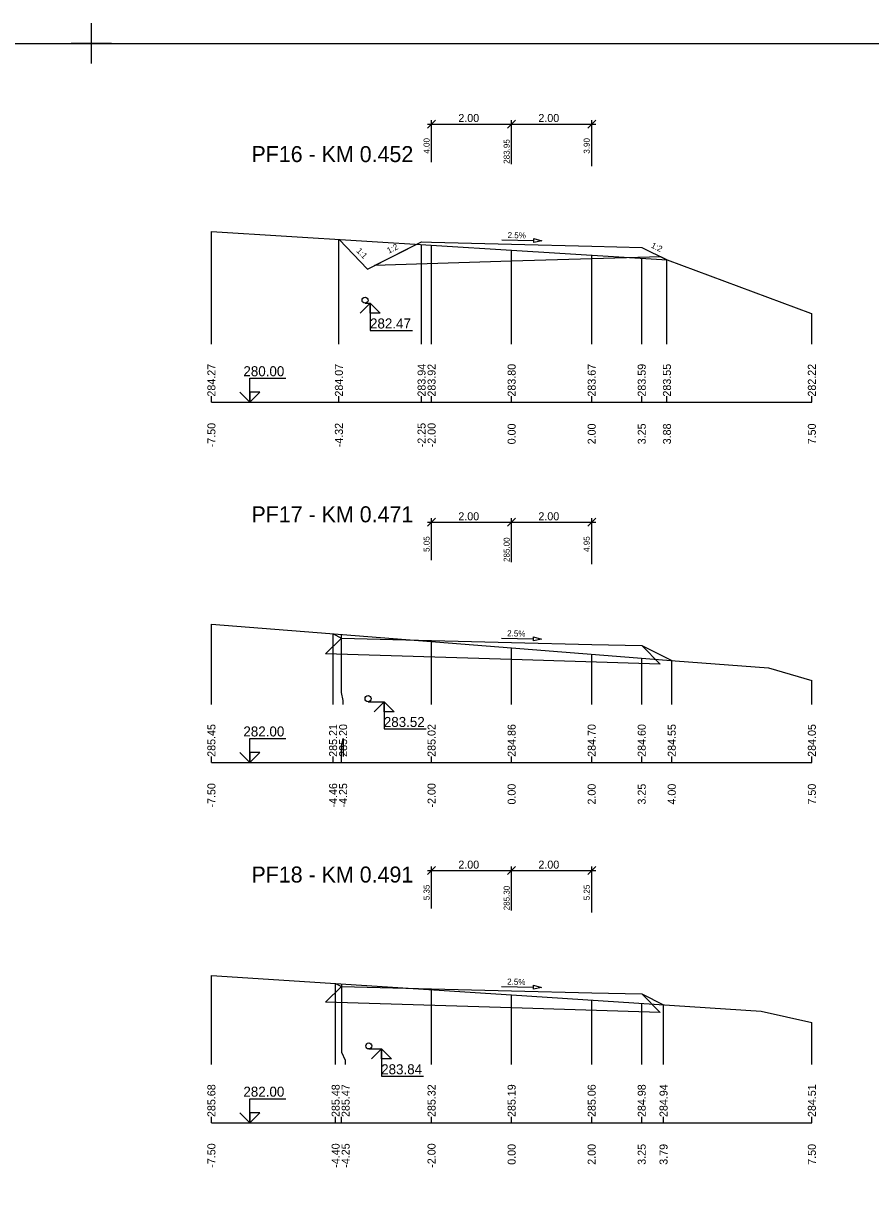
# Model space of a CAD drawing. Extents: x -5 to 1895, y -2 to 602.
# Drawn here: x 1033 to 1244.7, y 310.3 to 601.7 of the extents above; entities that cross this region are included whole.
import ezdxf

# ---------------------------------------------------------------- set-up
doc = ezdxf.new("R2010")
doc.units = 0
for name, color, linetype in [('KOTA', 7, 'Continuous'), ('KOTA_DELKY', 7, 'Continuous'), ('KOTA_DELKY_CONT', 7, 'Continuous'), ('KRIZENI', 7, 'Continuous'), ('NS_TELESO_VOZOVKY', 7, 'Continuous'), ('NS_V_PF', 7, 'Continuous'), ('REZY_PF_PUVODNI', 7, 'Continuous'), ('SESTAVY_REZU_PF', 7, 'Continuous'), ('SKLON', 7, 'Continuous'), ('SVK', 7, 'Continuous')]:
    doc.layers.add(name, color=color, linetype=linetype)

msp = doc.modelspace()

# ---------------------------------------------------------------- linework, layer by layer
for p, q in [((1050, 601.67), (1050, 591.67)), ((1050, 601.67), (1050, 591.67)), ((1050, 601.67), (1050, 591.67)), ((1050, 601.67), (1050, 591.67)), ((1050, 601.67), (1050, 591.67)), ((1050, 601.67), (1050, 591.67)), ((1050, 601.67), (1050, 591.67)), ((1050, 601.67), (1050, 591.67)), ((1050, 601.67), (1050, 591.67)), ((1050, 601.67), (1050, 591.67)), ((1050, 601.67), (1050, 591.67)), ((1050, 601.67), (1050, 591.67)), ((1050, 601.67), (1050, 591.67)), ((1050, 601.67), (1050, 591.67)), ((1050, 601.67), (1050, 591.67)), ((1050, 601.67), (1050, 591.67)), ((1050, 601.67), (1050, 591.67)), ((1050, 601.67), (1050, 591.67)), ((1050, 601.67), (1050, 591.67)), ((1050, 601.67), (1050, 591.67)), ((1050, 601.67), (1050, 591.67)), ((1050, 601.67), (1050, 591.67)), ((1050, 601.67), (1050, 591.67)), ((1050, 601.67), (1050, 591.67)), ((1050, 601.67), (1050, 591.67)), ((1050, 601.67), (1050, 591.67)), ((1050, 601.67), (1050, 591.67)), ((1050, 601.67), (1050, 591.67)), ((1050, 601.67), (1050, 591.67)), ((1050, 601.67), (1050, 591.67)), ((1050, 601.67), (1050, 591.67)), ((1050, 601.67), (1050, 591.67)), ((1050, 601.67), (1050, 591.67)), ((1050, 601.67), (1050, 591.67)), ((1050, 601.67), (1050, 591.67)), ((1050, 601.67), (1050, 591.67)), ((1050, 601.67), (1050, 591.67)), ((1050, 601.67), (1050, 591.67)), ((1050, 601.67), (1050, 591.67)), ((1050, 601.67), (1050, 591.67)), ((1050, 601.67), (1050, 591.67)), ((1050, 601.67), (1050, 591.67)), ((1050, 601.67), (1050, 591.67)), ((1050, 601.67), (1050, 591.67)), ((1050, 601.67), (1050, 591.67)), ((1050, 601.67), (1050, 591.67)), ((1050, 601.67), (1050, 591.67)), ((1050, 601.67), (1050, 591.67)), ((1050, 601.67), (1050, 591.67)), ((1050, 601.67), (1050, 591.67)), ((1050, 601.67), (1050, 591.67)), ((1050, 601.67), (1050, 591.67)), ((1050, 601.67), (1050, 591.67)), ((1050, 601.67), (1050, 591.67)), ((1055, 596.67), (1045, 596.67)), ((1055, 596.67), (1045, 596.67)), ((1055, 596.67), (1045, 596.67)), ((1055, 596.67), (1045, 596.67)), ((1055, 596.67), (1045, 596.67)), ((1055, 596.67), (1045, 596.67)), ((1055, 596.67), (1045, 596.67)), ((1055, 596.67), (1045, 596.67)), ((1055, 596.67), (1045, 596.67)), ((1055, 596.67), (1045, 596.67)), ((1055, 596.67), (1045, 596.67)), ((1055, 596.67), (1045, 596.67)), ((1055, 596.67), (1045, 596.67)), ((1055, 596.67), (1045, 596.67)), ((1055, 596.67), (1045, 596.67)), ((1055, 596.67), (1045, 596.67)), ((1055, 596.67), (1045, 596.67)), ((1055, 596.67), (1045, 596.67)), ((1055, 596.67), (1045, 596.67)), ((1055, 596.67), (1045, 596.67)), ((1055, 596.67), (1045, 596.67)), ((1055, 596.67), (1045, 596.67)), ((1055, 596.67), (1045, 596.67)), ((1055, 596.67), (1045, 596.67)), ((1055, 596.67), (1045, 596.67)), ((1055, 596.67), (1045, 596.67)), ((1055, 596.67), (1045, 596.67)), ((1055, 596.67), (1045, 596.67)), ((1055, 596.67), (1045, 596.67)), ((1055, 596.67), (1045, 596.67)), ((1055, 596.67), (1045, 596.67)), ((1055, 596.67), (1045, 596.67)), ((1055, 596.67), (1045, 596.67)), ((1055, 596.67), (1045, 596.67)), ((1055, 596.67), (1045, 596.67)), ((1055, 596.67), (1045, 596.67)), ((1055, 596.67), (1045, 596.67)), ((1055, 596.67), (1045, 596.67)), ((1055, 596.67), (1045, 596.67)), ((1055, 596.67), (1045, 596.67)), ((1055, 596.67), (1045, 596.67)), ((1055, 596.67), (1045, 596.67)), ((1055, 596.67), (1045, 596.67)), ((1055, 596.67), (1045, 596.67)), ((1055, 596.67), (1045, 596.67)), ((1055, 596.67), (1045, 596.67)), ((1055, 596.67), (1045, 596.67)), ((1055, 596.67), (1045, 596.67)), ((1055, 596.67), (1045, 596.67)), ((1055, 596.67), (1045, 596.67)), ((1055, 596.67), (1045, 596.67)), ((1055, 596.67), (1045, 596.67)), ((1055, 596.67), (1045, 596.67)), ((1055, 596.67), (1045, 596.67))]:
    msp.add_line(p, q)
msp.add_lwpolyline([(0, 596.67), (1890, 596.67), (1890, 2.67), (0, 2.67)], close=True)
at = {"layer": 'KOTA'}
for points in [[(1119.66, 531.75), (1117.16, 529.25), (1119.66, 531.75), (1119.66, 524.93), (1130.2, 524.93)], [(1118.38, 531.75), (1119.74, 531.75)], [(1119.66, 531.75), (1122.16, 529.25), (1119.66, 529.25), (1119.66, 531.75)], [(1119.66, 531.75), (1122.16, 529.25), (1119.66, 529.25)], [(1089.57, 507), (1087.07, 509.5), (1089.57, 507), (1089.57, 513), (1098.57, 513)], [(1089.57, 507), (1092.07, 509.5), (1089.57, 509.5), (1089.57, 507)], [(1089.57, 507), (1092.07, 509.5), (1089.57, 509.5)], [(1119.13, 432.19), (1123.12, 432.19)], [(1123.12, 432.19), (1120.62, 429.69), (1123.12, 432.19), (1123.12, 425.37), (1133.66, 425.37)], [(1123.12, 432.19), (1125.62, 429.69), (1123.12, 429.69), (1123.12, 432.19)], [(1123.12, 432.19), (1125.62, 429.69), (1123.12, 429.69)], [(1089.57, 417), (1087.07, 419.5), (1089.57, 417), (1089.57, 423), (1098.57, 423)], [(1089.57, 417), (1092.07, 419.5), (1089.57, 419.5), (1089.57, 417)], [(1089.57, 417), (1092.07, 419.5), (1089.57, 419.5)], [(1119.32, 345.43), (1122.46, 345.43)], [(1122.46, 345.43), (1119.96, 342.93), (1122.46, 345.43), (1122.46, 338.6), (1133, 338.6)], [(1122.46, 345.43), (1124.96, 342.93), (1122.46, 342.93), (1122.46, 345.43)], [(1122.46, 345.43), (1124.96, 342.93), (1122.46, 342.93)], [(1089.57, 327), (1087.07, 329.5), (1089.57, 327), (1089.57, 333), (1098.57, 333)], [(1089.57, 327), (1092.07, 329.5), (1089.57, 329.5), (1089.57, 327)], [(1089.57, 327), (1092.07, 329.5), (1089.57, 329.5)]]:
    msp.add_lwpolyline(points, dxfattribs=at)
at = {"layer": 'KOTA_DELKY'}
for points in [[(1134, 575.51), (1136, 577.51)], [(1135, 567.01), (1135, 577.51)], [(1154, 575.51), (1156, 577.51)], [(1154, 575.51), (1156, 577.51)], [(1155, 566.51), (1155, 577.51)], [(1155, 566.51), (1155, 577.51)], [(1174, 575.51), (1176, 577.51)], [(1175, 566.01), (1175, 577.51)], [(1134, 576.51), (1156, 576.51)], [(1154, 576.51), (1176, 576.51)], [(1134, 476.01), (1136, 478.01)], [(1135, 467.51), (1135, 478.01)], [(1154, 476.01), (1156, 478.01)], [(1154, 476.01), (1156, 478.01)], [(1155, 467.01), (1155, 478.01)], [(1155, 467.01), (1155, 478.01)], [(1174, 476.01), (1176, 478.01)], [(1175, 466.51), (1175, 478.01)], [(1134, 477.01), (1156, 477.01)], [(1154, 477.01), (1176, 477.01)], [(1134, 388.98), (1136, 390.98)], [(1135, 380.48), (1135, 390.98)], [(1154, 388.98), (1156, 390.98)], [(1154, 388.98), (1156, 390.98)], [(1155, 379.98), (1155, 390.98)], [(1155, 379.98), (1155, 390.98)], [(1174, 388.98), (1176, 390.98)], [(1175, 379.48), (1175, 390.98)], [(1134, 389.98), (1156, 389.98)], [(1154, 389.98), (1176, 389.98)]]:
    msp.add_lwpolyline(points, dxfattribs=at)
at = {"layer": 'KRIZENI'}
for centre in [(1118.38, 532.5), (1119.13, 432.94), (1119.32, 346.18)]:
    msp.add_circle(centre, 0.75, dxfattribs=at)
at = {"layer": 'NS_TELESO_VOZOVKY'}
for points in [[(1155, 546.51), (1175, 546.01), (1187.5, 545.69), (1193.8, 542.54), (1192.24, 543.32), (1155, 542.21), (1120.78, 541.18), (1132.5, 547.07), (1135, 547.01), (1155, 546.51)], [(1155, 447.01), (1175, 446.51), (1187.5, 446.2), (1192.1, 441.6), (1155, 442.71), (1108.53, 444.11), (1112.5, 448.08), (1135, 447.51), (1155, 447.01)], [(1155, 359.98), (1175, 359.48), (1187.5, 359.17), (1192.1, 354.57), (1155, 355.68), (1108.53, 357.08), (1112.5, 361.04), (1135, 360.48), (1155, 359.98)]]:
    msp.add_lwpolyline(points, dxfattribs=at)
at = {"layer": 'NS_V_PF'}
for points in [[(1111.88, 547.68), (1118.97, 540.27), (1132.5, 547.07), (1135, 547.01), (1155, 546.51), (1175, 546.01), (1187.5, 545.69), (1193.8, 542.54)], [(1110.4, 449.13), (1112.5, 448.08), (1135, 447.51), (1155, 447.01), (1175, 446.51), (1187.5, 446.2), (1195, 442.45)], [(1111.03, 361.78), (1112.5, 361.04), (1135, 360.48), (1155, 359.98), (1175, 359.48), (1187.5, 359.17), (1192.95, 356.45)]]:
    msp.add_lwpolyline(points, dxfattribs=at)
at = {"layer": 'REZY_PF_PUVODNI'}
for points in [[(1080, 549.68), (1155, 544.98), (1193.87, 542.54), (1197.41, 541.25), (1229.63, 529.25), (1230, 529.19)], [(1080, 451.53), (1155, 445.61), (1195.84, 442.39), (1219.19, 440.63), (1230, 437.52)], [(1080, 363.8), (1155, 358.92), (1217.3, 354.86), (1230, 352.06)]]:
    msp.add_lwpolyline(points, dxfattribs=at)
at = {"layer": 'SESTAVY_REZU_PF'}
for points in [[(1080, 507), (1230, 507)], [(1080, 417), (1230, 417)], [(1080, 327), (1230, 327)]]:
    msp.add_lwpolyline(points, dxfattribs=at)
at = {"layer": 'SKLON'}
for points in [[(1160.56, 547.87), (1162.54, 547.32), (1160.53, 546.87)], [(1160.46, 448.38), (1162.45, 447.83), (1160.43, 447.38)], [(1160.46, 361.35), (1162.45, 360.8), (1160.43, 360.35)]]:
    msp.add_lwpolyline(points, close=True, dxfattribs=at)
for points in [[(1160.56, 547.87), (1162.54, 547.32), (1160.53, 546.87), (1160.56, 547.87)], [(1152.55, 547.57), (1160.54, 547.37)], [(1152.45, 448.08), (1160.45, 447.88)], [(1160.46, 448.38), (1162.45, 447.83), (1160.43, 447.38), (1160.46, 448.38)], [(1160.46, 361.35), (1162.45, 360.8), (1160.43, 360.35), (1160.46, 361.35)], [(1152.45, 361.05), (1160.45, 360.85)]]:
    msp.add_lwpolyline(points, dxfattribs=at)
at = {"layer": 'SVK'}
for points in [[(1080, 521.5), (1080, 549.68)], [(1111.85, 521.5), (1111.85, 547.69)], [(1132.5, 521.5), (1132.5, 546.39)], [(1135, 521.5), (1135, 546.23)], [(1155, 521.5), (1155, 544.98)], [(1175, 521.5), (1175, 543.72)], [(1187.5, 521.5), (1187.5, 542.94)], [(1193.8, 521.5), (1193.8, 542.54)], [(1230, 521.5), (1230, 529.19)], [(1080, 507), (1080, 508.5)], [(1111.85, 507), (1111.85, 508.5)], [(1132.5, 507), (1132.5, 508.5)], [(1135, 507), (1135, 508.5)], [(1155, 507), (1155, 508.5)], [(1175, 507), (1175, 508.5)], [(1187.5, 507), (1187.5, 508.5)], [(1193.8, 507), (1193.8, 508.5)], [(1230, 507), (1230, 508.5)], [(1080, 431.5), (1080, 451.53)], [(1110.4, 431.5), (1110.4, 449.13)], [(1112.9, 431.5), (1112.9, 432.5), (1112.5, 434.5), (1112.5, 448.96)], [(1135, 431.5), (1135, 447.19)], [(1155, 431.5), (1155, 445.61)], [(1175, 431.5), (1175, 444.03)], [(1187.5, 431.5), (1187.5, 443.04)], [(1195, 431.5), (1195, 442.45)], [(1230, 431.5), (1230, 437.52)], [(1112.5, 417), (1112.5, 421), (1112.9, 423), (1112.9, 418.5)], [(1080, 417), (1080, 418.5)], [(1110.4, 417), (1110.4, 418.5)], [(1135, 417), (1135, 418.5)], [(1155, 417), (1155, 418.5)], [(1175, 417), (1175, 418.5)], [(1187.5, 417), (1187.5, 418.5)], [(1195, 417), (1195, 418.5)], [(1230, 417), (1230, 418.5)], [(1080, 341.5), (1080, 363.8)], [(1111.03, 341.5), (1111.03, 361.78)], [(1113.53, 341.5), (1113.53, 342.5), (1112.55, 344.5), (1112.55, 361.68)], [(1135, 341.5), (1135, 360.22)], [(1155, 341.5), (1155, 358.92)], [(1175, 341.5), (1175, 357.61)], [(1187.5, 341.5), (1187.5, 356.8)], [(1192.95, 341.5), (1192.95, 356.45)], [(1230, 341.5), (1230, 352.06)], [(1080, 327), (1080, 328.5)], [(1111.03, 327), (1111.03, 328.5)], [(1112.53, 326.99), (1112.53, 328.35), (1112.53, 328.47), (1112.53, 328.47)], [(1135, 327), (1135, 328.5)], [(1155, 327), (1155, 328.5)], [(1175, 327), (1175, 328.5)], [(1187.5, 327), (1187.5, 328.5)], [(1192.95, 327), (1192.95, 328.5)], [(1230, 327), (1230, 328.5)]]:
    msp.add_lwpolyline(points, dxfattribs=at)

# ---------------------------------------------------------------- texts
at = {"layer": 'KOTA'}
for s, p in [('282.47', (1119.62, 525.43)), ('280.00', (1087.99, 513.5)), ('283.52', (1123.07, 425.87)), ('282.00', (1087.99, 423.5)), ('283.84', (1122.41, 339.1)), ('282.00', (1087.99, 333.5))]:
    msp.add_text(s, height=2.5, dxfattribs=at).set_placement(p)
at = {"layer": 'KOTA_DELKY'}
for p in [(1141.69, 577.01), (1161.69, 577.01), (1141.69, 477.51), (1161.69, 477.51), (1141.69, 390.48), (1161.69, 390.48)]:
    msp.add_text('2.00', height=2, dxfattribs=at).set_placement(p)
at = {"layer": 'KOTA_DELKY_CONT'}
for s, p in [('4.00', (1134.5, 569.1)), ('283.95', (1154.5, 566.58)), ('3.90', (1174.5, 569.1)), ('5.05', (1134.5, 469.6)), ('285.00', (1154.5, 467.09)), ('4.95', (1174.5, 469.6)), ('5.35', (1134.5, 382.57)), ('285.30', (1154.5, 380.06)), ('5.25', (1174.5, 382.57))]:
    msp.add_text(s, height=1.5, rotation=90, dxfattribs=at).set_placement(p)
at = {"layer": 'SESTAVY_REZU_PF'}
for s, p in [('PF16 - KM 0.452', (1090, 567)), ('PF17 - KM 0.471', (1090, 477)), ('PF18 - KM 0.491', (1090, 387))]:
    msp.add_text(s, height=4, dxfattribs=at).set_placement(p)
at = {"layer": 'SKLON'}
for s, rotation, p in [('2.5%', 358.5679, (1153.97, 548.03)), ('1:1', 313.6939, (1116.11, 544.71)), ('1:2', 26.6859, (1124.32, 544.08)), ('1:2', 333.4349, (1189.69, 545.72)), ('2.5%', 358.5679, (1153.87, 448.54)), ('2.5%', 358.5679, (1153.87, 361.51))]:
    msp.add_text(s, height=1.5, rotation=rotation, dxfattribs=at).set_placement(p)
at = {"layer": 'SVK'}
for s, p in [(' 284.27', (1081, 507.67)), (' 284.07', (1112.85, 507.67)), (' 283.94', (1133.5, 507.67)), (' 283.92', (1136, 507.67)), (' 283.80', (1156, 507.67)), (' 283.67', (1176, 507.67)), (' 283.59', (1188.5, 507.67)), (' 283.55', (1194.8, 507.67)), (' 282.22', (1231, 507.67)), (' -7.50', (1081, 495)), (' -4.32', (1112.85, 495)), (' -2.25', (1133.5, 495)), (' -2.00', (1136, 495)), ('  0.00', (1156, 495)), ('  2.00', (1176, 495)), ('  3.25', (1188.5, 495)), ('  3.88', (1194.8, 495)), ('  7.50', (1231, 495)), (' 285.45', (1081, 417.67)), (' 285.21', (1111.4, 417.67)), (' 285.20', (1113.9, 417.67)), (' 285.02', (1136, 417.67)), (' 284.86', (1156, 417.67)), (' 284.70', (1176, 417.67)), (' 284.60', (1188.5, 417.67)), (' 284.55', (1196, 417.67)), (' 284.05', (1231, 417.67)), (' -7.50', (1081, 405)), (' -4.46', (1111.4, 405)), (' -4.25', (1113.9, 405)), (' -2.00', (1136, 405)), ('  0.00', (1156, 405)), ('  2.00', (1176, 405)), ('  3.25', (1188.5, 405)), ('  4.00', (1196, 405)), ('  7.50', (1231, 405)), (' 285.68', (1081, 327.67)), (' 285.48', (1112.03, 327.67)), (' 285.47', (1114.53, 327.67)), (' 285.32', (1136, 327.67)), (' 285.19', (1156, 327.67)), (' 285.06', (1176, 327.67)), (' 284.98', (1188.5, 327.67)), (' 284.94', (1193.95, 327.67)), (' 284.51', (1231, 327.67)), (' -7.50', (1081, 315)), (' -4.40', (1112.03, 315)), (' -4.25', (1114.53, 315)), (' -2.00', (1136, 315)), ('  0.00', (1156, 315)), ('  2.00', (1176, 315)), ('  3.25', (1188.5, 315)), ('  3.79', (1193.95, 315)), ('  7.50', (1231, 315))]:
    msp.add_text(s, height=2, rotation=90, dxfattribs=at).set_placement(p)

doc.saveas('drawing.dxf')
